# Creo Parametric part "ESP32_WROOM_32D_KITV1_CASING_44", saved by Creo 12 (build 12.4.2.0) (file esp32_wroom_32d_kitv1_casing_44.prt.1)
Units: Custom; MM, KILOGRAM, SECS

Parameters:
  PTC_WM_ITERATION = "0"
  PTC_WM_VERSION = "-.0"
  PTC_WM_LIFECYCLE_STATE = "In Work"
  PTC_WM_LIFECYCLE = "MO_CADDocument"
  PTC_WM_CREATED_BY = "Maximilian Roepper (Z0017RMS: MO)"
  PTC_WM_CREATED_ON = "18-Sep-26 11:36:42 AM"
  PTC_WM_MODIFIED_BY = "Maximilian Roepper (Z0017RMS: MO)"
  PTC_WM_MODIFIED_ON = "18-Sep-26 11:36:46 AM"
  PDMLINKNUMBER = "PDM000071455198"
  PTC_WM_NAME = "esp32_wroom_32d_kitv1_casing_44.prt"
  PTC_WM_NUMBER = "PDM000071455198"

Other parameters: WEIGHT, WEIGHT_FACTOR, WEIGHT_ADD, _MASS_TEMP, _DIFF_TEMP, MC_ERRORS, SUPPLIER

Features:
  1. coordinate system
  2. datum plane "PRT_YZ"
  3. datum plane "PRT_XY"
  4. datum plane "PRT_XZ"
  5. coordinate system
  6. datum axis
  7. datum axis
  8. datum axis
  9. coordinate system
  10. imported feature
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
Other named items: PRT, SIEMENS_MO, DRW_VIEW_ORG, PRT_X, PRT_Y, PRT_Z, CS0, ROUGH_GROB

Layers: 00_STD_CSYS-KSYS, 01_STD_PLANES-EBENEN, 02_STD_AXES-ACHSEN, 03_STD_CSYS-KSYS, 24_IMPORT_FEAT-IMPORT_KE

Surfaces: 6 plane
